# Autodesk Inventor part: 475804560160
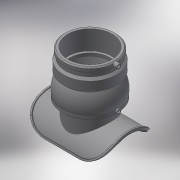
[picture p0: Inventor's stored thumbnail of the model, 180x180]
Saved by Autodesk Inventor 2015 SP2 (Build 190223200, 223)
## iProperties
Created: 2017-08
Part Number: 475804560160
Material: Generic
Description: PLASSON WASTEWATER SADDLE 355-560x160 EF ADJUSTABLE INLET
Document SubType Name: Modeling
Designer: Кирилл
Density: 1 g/cm^3
Appearance: Default
Author: Кирилл
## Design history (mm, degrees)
derived "475804.ipt"
feature "Solid1::475804.ipt"
feature "Solid2::475804.ipt"
tag "TaggingFeature1"
body "Solid1"
body "Solid2"
other parameters: "d0" = 161.6, "d3" = 45 deg, "d4" = 184, "d5" = 176, "d6" = 142.208, "d7" = 129.28, "d8" = 144, "d13" = 45 deg, "d15" = 135 deg, "d17" = 192, "d18" = 45 deg, "d19" = 80.8, "d22" = 4, "d23" = 16.16, "d25" = 45 deg, "d26" = 15 deg, "d27" = 262.6, "d28" = 136, "d29" = 156.8, "d32" = 202, "d37" = 0, "d38" = 263, "d39" = 131.5, "d40" = 576.8, "d42" = 0, "d52" = 105.2, "d53" = 6.575, "d55" = 1.052, "d56" = 224, "d57" = 0, "d58" = 105, "d59" = 15, "d61" = 5 deg, "d62" = 15, "d65" = 4, "d66" = 4, "d67" = 14, "d68" = 0, "d69" = 3, "d70" = 0, "B_" = 263, "H_" = 202, "A_" = 105, "d21" = 4
